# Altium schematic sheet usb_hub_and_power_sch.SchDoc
size 431 x 279 mm; Date: Not shown in title block; ApprovedBy: Not shown in title block; CheckedBy: Not shown in title block; Author: Not shown in title block; CompanyName: Not shown in title block; Engineer: Not shown in title block; Organization: Not shown in title block; Address1: Not shown in title block; Address2: Not shown in title block; Address3: Not shown in title block; Address4: Not shown in title block; DocumentNumber: 4; Revision: Use project parameter SCH_Rev; SheetNumber: 1; SheetTotal: 4; PageSetup: Record=PageOptions|CenterHorizontal=True|CenterVertical=True|PrintScale=1.00|XCorrection=1.00|YCorrection=1.00|PrintKind=0|BorderSize=5000000|LeftOffset=0|BottomOffset=0|Orientation=2|PaperLength=1000|PaperWidth=1000|Scale=100|PaperSource=15|PrintQuality=600|MediaType=1|DitherType=10|PaperKind=Letter|PrintScaleMode=1
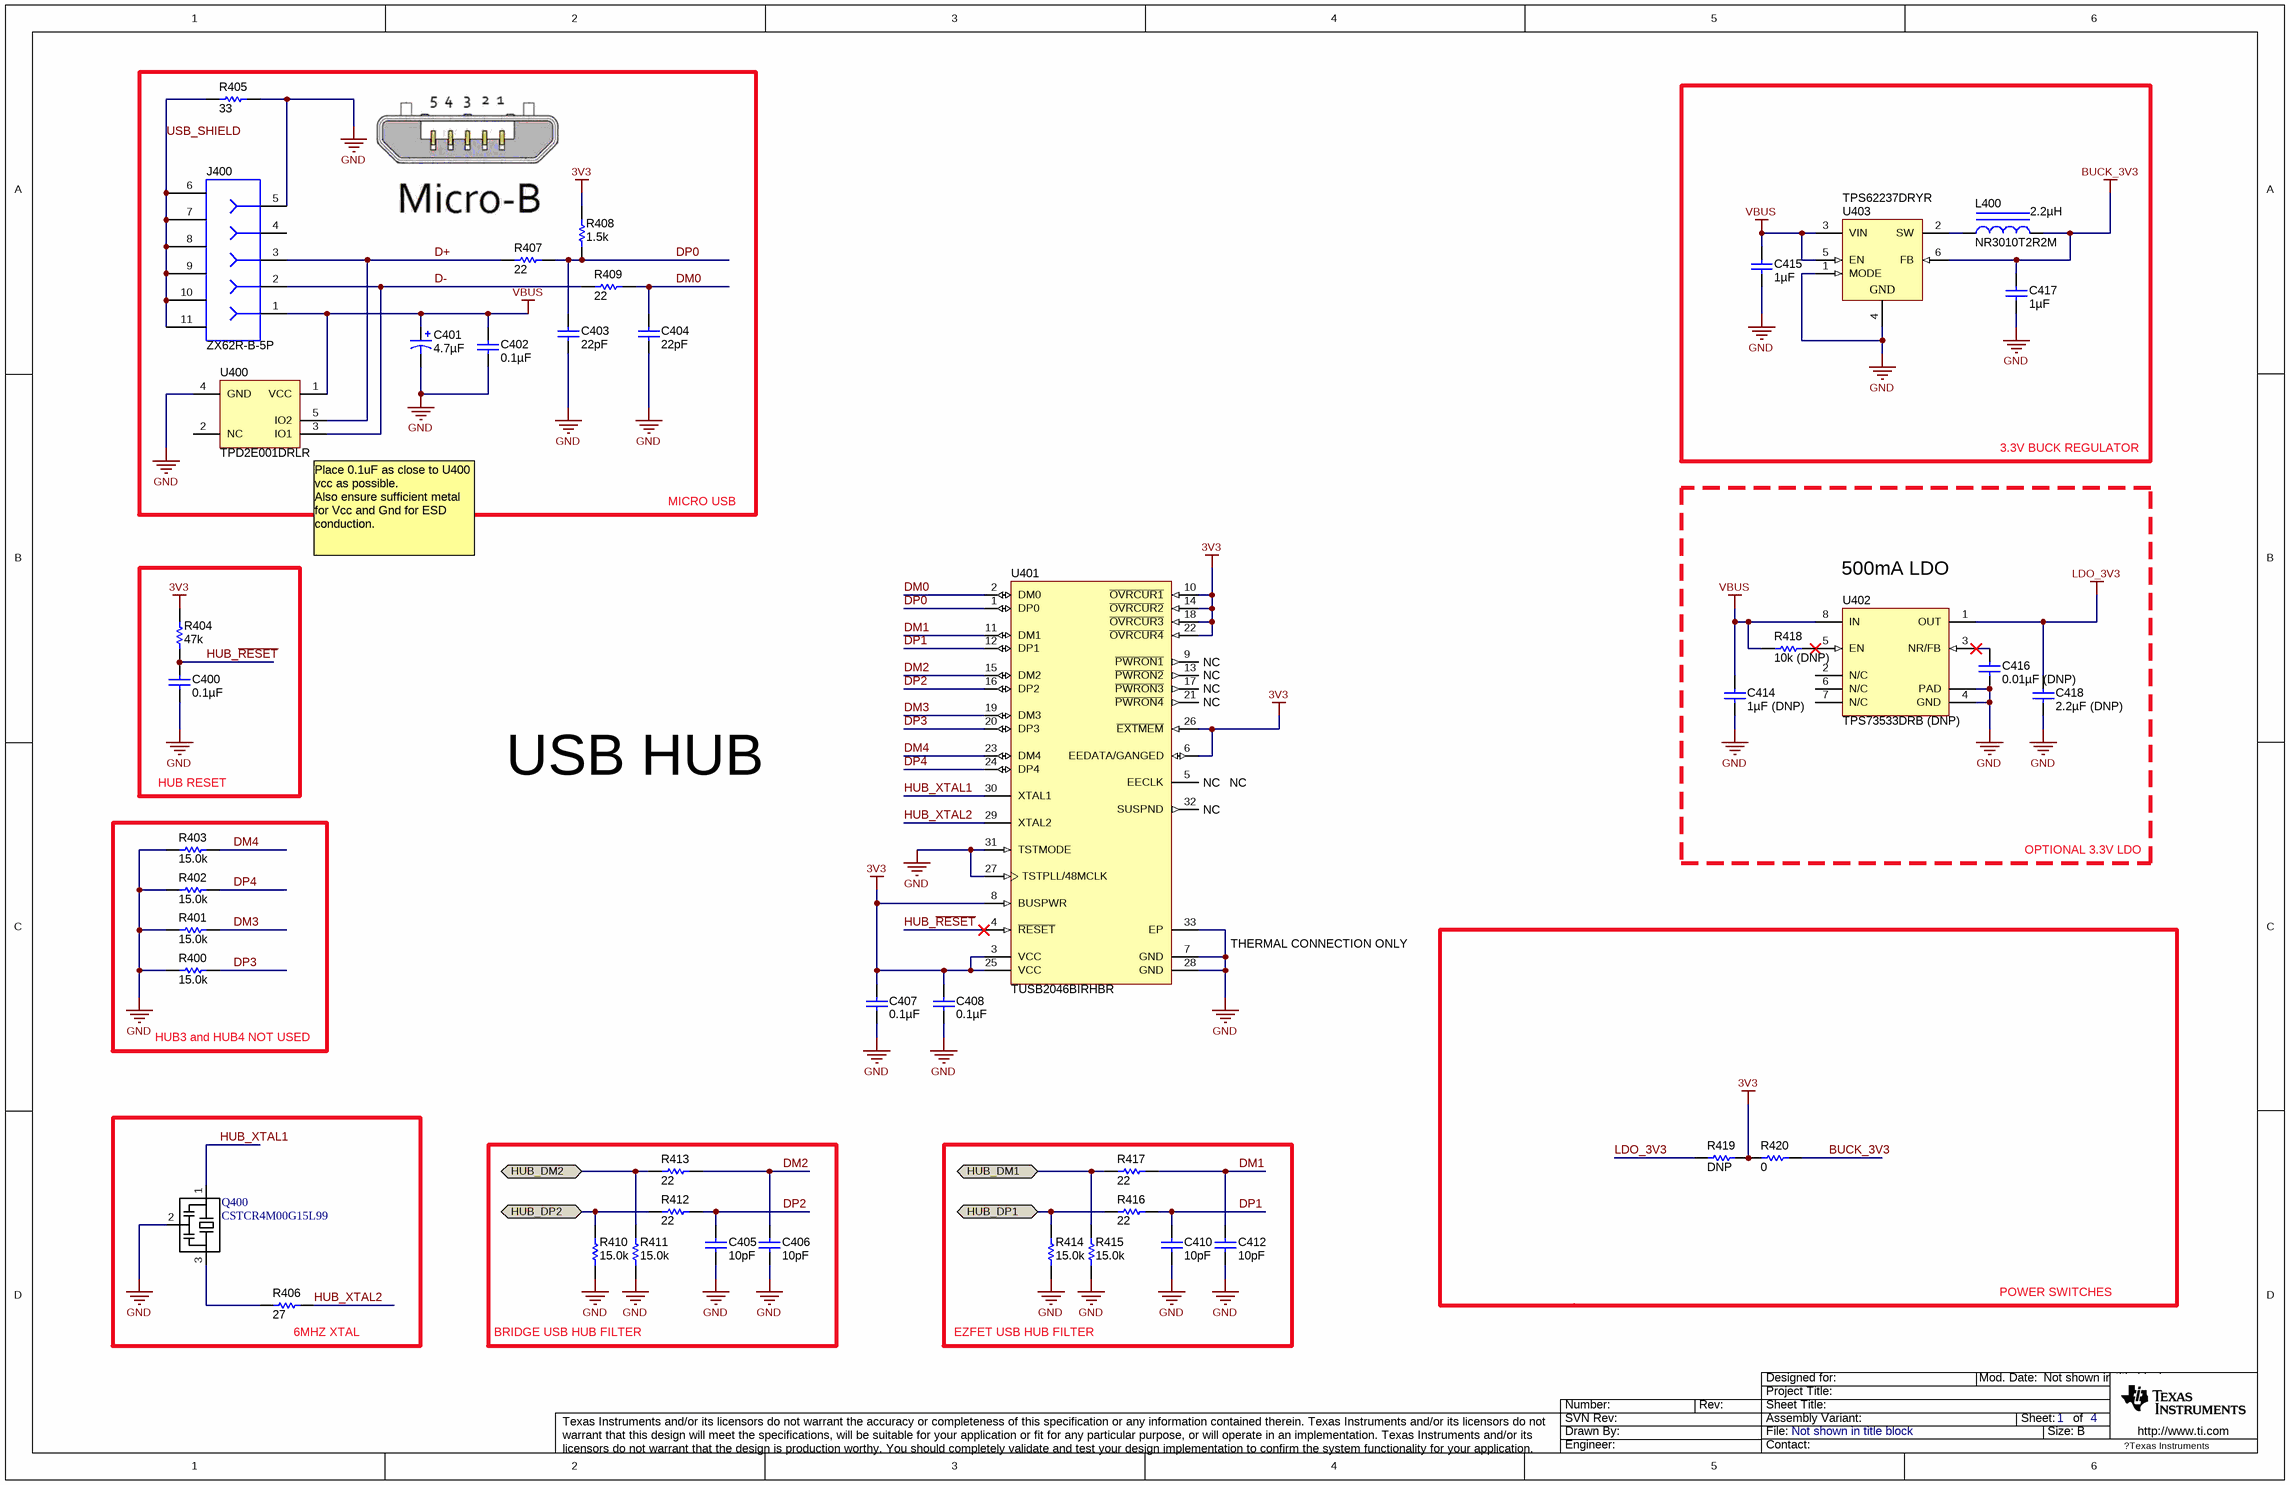
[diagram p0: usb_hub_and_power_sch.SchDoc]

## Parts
C400  ValueDisplayed: 0.1µF  [0402]  (hidden comment: GRM155R61C104KA88D)
C401  ValueDisplayed: 4.7µF  [0805]  (hidden comment: 293D475X9010A2TE3)
C402  ValueDisplayed: 0.1µF  [0402]  (hidden comment: GRM155R61C104KA88D)
C403  ValueDisplayed: 22pF  [0402]  (hidden comment: GRM1555C1H220JA01D)
C404  ValueDisplayed: 22pF  [0402]  (hidden comment: GRM1555C1H220JA01D)
C405  ValueDisplayed: 10pF  [0402]  (hidden comment: GRM1555C1H100JA01D)
C406  ValueDisplayed: 10pF  [0402]  (hidden comment: GRM1555C1H100JA01D)
C407  ValueDisplayed: 0.1µF  [0402]  (hidden comment: GRM155R61C104KA88D)
C408  ValueDisplayed: 0.1µF  [0402]  (hidden comment: GRM155R61C104KA88D)
C410  ValueDisplayed: 10pF  [0402]  (hidden comment: GRM1555C1H100JA01D)
C412  ValueDisplayed: 10pF  [0402]  (hidden comment: GRM1555C1H100JA01D)
C414  ValueDisplayed: 1µF (DNP)  [0603]  (hidden comment: C0603C105K8PACTU)
C415  ValueDisplayed: 1µF  [0603]  (hidden comment: GRM21BR71A105KA01L)
C416  ValueDisplayed: 0.01µF (DNP)  [0402]  (hidden comment: GRM155R61C103KA01D)
C417  ValueDisplayed: 1µF  [0603]  (hidden comment: GRM21BR71A105KA01L)
C418  ValueDisplayed: 2.2µF (DNP)  [0603]  (hidden comment: C0603C225K8PACTU)
J400  ZX62R-B-5P  [CONN_USB_micro_ZX62R-B-5PA]
L400  NR3010T2R2M  ValueDisplayed: 2.2µH  [INDUCTOR_2.2UH_SMD]
Q400  CSTCR4M00G15L99  [CSTCR CERAMIC RESONATOR - MURATA]
R400  value 15.0k  [0402]  (hidden comment: CRCW040215K0FKED)
R401  value 15.0k  [0402]  (hidden comment: CRCW040215K0FKED)
R402  value 15.0k  [0402]  (hidden comment: CRCW040215K0FKED)
R403  value 15.0k  [0402]  (hidden comment: CRCW040215K0FKED)
R404  value 47k  [0402]  (hidden comment: CRCW040247K0JNED)
R405  value 33  [0402]  (hidden comment: CRCW040233R0JNED)
R406  value 27  [0402]  (hidden comment: CRCW040227R0JNED)
R407  value 22  [0402]  (hidden comment: CRCW040222R0JNED)
R408  value 1.5k  [0402]  (hidden comment: CRCW04021K50JNED)
R409  value 22  [0402]  (hidden comment: CRCW040222R0JNED)
R410  value 15.0k  [0402]  (hidden comment: CRCW040215K0FKED)
R411  value 15.0k  [0402]  (hidden comment: CRCW040215K0FKED)
R412  value 22  [0402]  (hidden comment: CRCW040222R0JNED)
R413  value 22  [0402]  (hidden comment: CRCW040222R0JNED)
R414  value 15.0k  [0402]  (hidden comment: CRCW040215K0FKED)
R415  value 15.0k  [0402]  (hidden comment: CRCW040215K0FKED)
R416  value 22  [0402]  (hidden comment: CRCW040222R0JNED)
R417  value 22  [0402]  (hidden comment: CRCW040222R0JNED)
R418  value 10k (DNP)  [0402]  (hidden comment: CRCW040210K0JNED)
R419  value DNP  [0402]  (hidden comment: CRCW040222R0JNED)
R420  value 0  [0402]  (hidden comment: CRCW040222R0JNED)
U400  TPD2E001DRLR  [DRL0005A]
U401  TUSB2046BIRHBR  [RHB0032E]
U402  TPS73533DRB (DNP)  [DRB0008A]
U403  TPS62237DRYR  [DRY0006A]

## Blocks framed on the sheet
MICRO USB: C401-C404 J400 R405 R407-R409 U400
3.3V BUCK REGULATOR: C415 C417 L400 U403
500mA LDO: C414 C416 C418 R418 U402
HUB RESET: C400 R404
HUB3 and HUB4 NOT USED: R400-R403
POWER SWITCHES: R419 R420
6MHZ XTAL: Q400 R406
BRIDGE USB HUB FILTER: C405 C406 R410-R413
EZFET USB HUB FILTER: C410 C412 R414-R417

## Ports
HUB_DM1 (bidir), HUB_DM2 (bidir), HUB_DP1 (bidir), HUB_DP2 (bidir)

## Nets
3V3: C407.1 C408.1 R404.2 R408.2 R419.1 R420.1 U401.3(VCC) U401.6(EEDATA/GANGED) U401.8(BUSPWR) U401.10(~{OVRCUR1}) U401.14(~{OVRCUR2}) U401.18(~{OVRCUR3}) U401.22(~{OVRCUR4}) U401.25(VCC) U401.26(~{EXTMEM})
BUCK_3V3: C417.1 L400.2 R420.2 U403.6(FB)
GND: C400.2 C401.2(-) C402.2 C403.2 C404.2 C405.2 C406.2 C407.2 C408.2 C410.2 C412.2 C414.2 C415.2 C416.2 C417.2 C418.2 J400.5 Q400.2 R400.1 R401.1 R402.1 R403.1 R405.2 R410.1 R411.1 R414.1 R415.1 U400.4(GND) U401.7(GND) U401.27(TSTPLL/48MCLK) U401.28(GND) U401.31(TSTMODE) U401.33(EP) U402.4(GND) U402.9(PAD) U403.1(MODE) U403.4(GND)
LDO_3V3: C418.1 R419.2 U402.1(OUT)
VBUS: C401.1(+) C402.1 C414.1 C415.1 J400.1 R418.1 U400.1(VCC) U402.8(IN) U403.3(VIN) U403.5(EN)
D+: J400.3 R407.1 U400.5(IO2)
D-: J400.2 R409.1 U400.3(IO1)
DM0: C404.1 R409.2 U401.2(DM0)
DM1: C412.1 R417.2 U401.11(DM1)
DM2: C406.1 R413.2 U401.15(DM2)
DM3: R401.2 U401.19(DM3)
DM4: R403.2 U401.23(DM4)
DP0: C403.1 R407.2 R408.1 U401.1(DP0)
DP1: C410.1 R416.2 U401.12(DP1)
DP2: C405.1 R412.2 U401.16(DP2)
DP3: R400.2 U401.20(DP3)
DP4: R402.2 U401.24(DP4)
HUB_DM1: R415.2 R417.1 ; port HUB_DM1
HUB_DM2: R411.2 R413.1 ; port HUB_DM2
HUB_DP1: R414.2 R416.1 ; port HUB_DP1
HUB_DP2: R410.2 R412.1 ; port HUB_DP2
HUB_~{RESET}: C400.1 R404.1 U401.4(~{RESET})
HUB_XTAL1: Q400.1 U401.30(XTAL1)
HUB_XTAL2: R406.2 U401.29(XTAL2)
USB_SHIELD: J400.6 J400.7 J400.8 J400.9 J400.10 J400.11 R405.1
NetC416_1: C416.1 U402.3(NR/FB)
NetL400_1: L400.1 U403.2(SW)
NetQ400_3: Q400.3 R406.1
NetR418_2: R418.2 U402.5(EN)

Not connected (* = marked no-connect by the designer): J400 4; U400 2(NC); U401 5(EECLK) 9(~{PWRON1}) 13(~{PWRON2}) 17(~{PWRON3}) 21(~{PWRON4}) 32(SUSPND); U402 2(N/C) 6(N/C) 7(N/C)

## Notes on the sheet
- (near U400) Place 0.1uF as close to U400 vcc as possible.
  Also ensure sufficient metal for Vcc and Gnd for ESD conduction.
- (near U401) NC
- USB HUB
- NC
- OPTIONAL 3.3V LDO
- THERMAL CONNECTION ONLY

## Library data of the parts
C400 C402 C407 C408 = GRM155R61C104KA88D: CAP, CERM, 0.1uF, 16V, +/-10%, X5R, 0402; Manufacturer: MuRata; Polarized: N; CompType: Capacitor; U/M: EA; Cap_F: 0.0000001; Tolerance_%: 10; Value1: Unknown; VDC_V: 16; TaMin_C: -55; TaMax_C: 85
C401 = 293D475X9010A2TE3: CAP, TA, 4.7uF, 10V, +/-10%, 5 ohm, SMD; Manufacturer: Vishay-Sprague; Polarized: Y; CompType: Capacitor; U/M: EA; Cap_F: 0.0000047; Tolerance_%: 10; Value1: 5 ohm; ESR_Ohm: 5; IRMS_A: 0.12; TaMin_C: -55; TaMax_C: 125; Cap_Case: A
C403 C404 = GRM1555C1H220JA01D: CAP, CERM, 22pF, 50V, +/-5%, C0G/NP0, 0402; Manufacturer: MuRata; Polarized: N; CompType: Capacitor; U/M: EA; Cap_F: 0.000000000022; Tolerance_%: 5; Value1: Unknown; VDC_V: 50; TaMin_C: -55; TaMax_C: 125
C405 C406 C410 C412 = GRM1555C1H100JA01D: CAP, CERM, 10pF, 50V, +/-5%, C0G/NP0, 0402; Manufacturer: MuRata; Polarized: N; CompType: Capacitor; U/M: EA; Cap_F: 0.00000000001; Tolerance_%: 5; Value1: Unknown; VDC_V: 50; TaMin_C: -55; TaMax_C: 125
C414 = C0603C105K8PACTU: CAP, CERM, 1uF, 10V, +/-10%, X5R, 0603; Manufacturer: Kemet; Polarized: N; CompType: Capacitor; U/M: EA; Cap_F: 0.000001; Tolerance_%: 10; Value1: Unknown; TaMin_C: -55; TaMax_C: 85
C415 C417 = GRM21BR71A105KA01L: CAP, CERM, 1uF, 10V, +/-10%, X7R, 0805; Manufacturer: MuRata; Polarized: N; CompType: Capacitor; U/M: EA; Cap_F: 0.000001; Tolerance_%: 10; ESR_Ohm: 0.007; Value1: 0.007 ohm; TaMin_C: -55; TaMax_C: 125; Cap_Case: 0805
C416 = GRM155R61C103KA01D: CAP, CERM, 0.01uF, 16V, +/-10%, X5R, 0402; Manufacturer: MuRata; Polarized: N; CompType: Capacitor; U/M: EA; Cap_F: 0.00000001; Tolerance_%: 10; Value1: Unknown; VDC_V: 16; TaMin_C: -55; TaMax_C: 85
C418 = C0603C225K8PACTU: CAP, CERM, 2.2uF, 10V, +/-10%, X5R, 0603; Manufacturer: Kemet; Polarized: N; CompType: Capacitor; U/M: EA; Cap_F: 0.0000022; Tolerance_%: 10; Value1: Unknown; TaMin_C: -55; TaMax_C: 85
J400 = ZX62R-B-5P: Connector, micro USB Type B, Reverse, Receptacle, SMD; Manufacturer: Hirose Electric Co. Ltd.; SymbolCreator: a0411947; U/M: EA
L400 = NR3010T2R2M: Inductor, 2.2uH, 20%, 1.1A,, 0.095 ohm, SMD; Manufacturer: Taiyo Yuden; Ind_H: 2.2E-6; Imax_A: 2.2; Irms: 2.2A @ C rise; Isat: 3A @ % inductance drop; DCR_ohm: 0.042; Material: Powdered Iron; U/M: EA
Q400 = MURATA-FILTER_CSTCR6M00G15
R400-R403 R410 R411 R414 R415 = CRCW040215K0FKED: RES, 15.0k ohm, 1%, 0.063W, 0402; Manufacturer: Vishay-Dale; CompType: Resistor; Res_ohm: 15000; Value_Code: 15k0; Tolerance_%: 1; Power_W: 0.063; VDC_V: 50; TempCo: 100 ppm/C; EIA_Code: E96; U/M: EA
R404 = CRCW040247K0JNED: RES, 47k ohm, 5%, 0.063W, 0402; Manufacturer: Vishay-Dale; CompType: Resistor; Res_ohm: 47000; Value_Code: 47k0; Tolerance_%: 5; Power_W: 0.063; VDC_V: 50; TempCo: 200 ppm/C; EIA_Code: E24; U/M: EA
R405 = CRCW040233R0JNED: RES, 33 ohm, 5%, 0.063W, 0402; Manufacturer: Vishay-Dale; CompType: Resistor; Value_Code: 33R0; Tolerance_%: 5; Power_W: 0.063; VDC_V: 50; TempCo: 200 ppm/C; EIA_Code: E24; U/M: EA
R406 = CRCW040227R0JNED: RES, 27 ohm, 5%, 0.063W, 0402; Manufacturer: Vishay-Dale; CompType: Resistor; Value_Code: 27R0; Tolerance_%: 5; Power_W: 0.063; VDC_V: 50; TempCo: 200 ppm/C; EIA_Code: E24; U/M: EA
R407 R409 R412 R413 R416 R417 = CRCW040222R0JNED: RES, 22 ohm, 5%, 0.063W, 0402; Manufacturer: Vishay-Dale; CompType: Resistor; Value_Code: 22R0; Tolerance_%: 5; Power_W: 0.063; VDC_V: 50; TempCo: 200 ppm/C; EIA_Code: E24; U/M: EA
R408 = CRCW04021K50JNED: RES, 1.5k ohm, 5%, 0.063W, 0402; Manufacturer: Vishay-Dale; CompType: Resistor; Res_ohm: 1500; Value_Code: 1k50; Tolerance_%: 5; Power_W: 0.063; VDC_V: 50; TempCo: 200 ppm/C; EIA_Code: E24; U/M: EA
R418 = CRCW040210K0JNED: RES, 10k ohm, 5%, 0.063W, 0402; Manufacturer: Vishay-Dale; CompType: Resistor; Res_ohm: 10000; Value_Code: 10k0; Tolerance_%: 5; Power_W: 0.063; VDC_V: 50; TempCo: 200 ppm/C; EIA_Code: E24; U/M: EA
R419 R420 = CRCW040222R0JNED: RES, 22 ohm, 5%, 0.063W, 0402; Manufacturer: Vishay-Dale; CompType: Resistor; Res_ohm: 22; Value_Code: 22R0; Tolerance_%: 5; Power_W: 0.063; VDC_V: 50; TempCo: 200 ppm/C; EIA_Code: E24; U/M: EA
U400 = TPD2E001DRLR: Low-Capacitance + / - 15 kV ESD-Protection Array for High-Speed Data Interfaces, 2 Channels, -40 to +85 degC, 5-pin SOT (DRL), Green (RoHS & no Sb/Br); Manufacturer: Texas Instruments; Alternate Manufacturer: None; Alternate PartNumber: Equivalent; Breakdown Voltage(Min)(V): 11; IEC 61000-4-2 Air-Gap(+/- kV): 15; IEC 61000-4-2 Contact(+/- kV): 8; IO Capacitance(Typ)(pF): 1.5; IO Leakage Current(nA): 1; SubFamily: ESD Solution; USB High Speed: TRUE
U401 = TUSB2046BIRHBR: 4-Port Full-Speed USB Hub, 3.3V, -40 to 85 degC, 32-Pin QFN (RHB), Green (RoHS & no Sb/Br); Manufacturer: Texas Instruments; Alternate Manufacturer: None; Alternate PartNumber: Equivalent; SubFamily: USB Hub Controller; USB Speed: Full; USB Full Speed: True; Supply Voltage(s)(V): 3.3
U402 = TPS73533DRB: 500mA, Low Quiescent Current, Ultra-Low Noise, High PSRR Low-Dropout Linear Regulator, DRB0008A; Alternate Manufacturer: None; Manufacturer: Texas Instruments; SymbolCreator: a0411947; CompType: IC; U/M: EA
U403 = TPS62237DRYR: Buck Step Down Regulator with 2.05 to 6 V Input and 3.3 V Output, -40 to 85 degC, 6-Pin SON (DRY), Green (RoHS & no Sb/Br); Manufacturer: Texas Instruments; Alternate Manufacturer: None; Alternate PartNumber: Equivalent; Duty Cycle(Max)(%): 100; Iout(Max)(A): 0.5; Iq(Typ)(mA): 0.022; Preset Vout(V): 3.3; Rating: Catalog; Regulated Outputs(#): 1; SubFamily: Step-Down Regulator; Switch Current Limit(Typ)(A): 0.84; Synchronous Rectification: TRUE; Vin(Max)(V): 6; Vin(Min)(V): 2.05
